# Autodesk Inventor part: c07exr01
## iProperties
Shininess: 77.0
Length Units: 11269
Angle Units: 11279
Time Units: 11290
Mass Units: 11283
Length Display Precision: 3
Angle Display Precision: 2
Created: 2002-01
Part Number: c07exr01
Document SubType Name: Modeling
Designer: ***
Density: 1 g/cm^3
Density: 0.0
Volumn: 0.0
Area: 0.0
PropertySet Name: Model Information
Control State: 0
Master: False
Checked Out: False
Author: ***
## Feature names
1. Sweep1
2. Shell1
3. Extrusion5
4. Extrusion6
5. Hole5
6. Rectangular Pattern5
7. Hole6
8. Rectangular Pattern6
